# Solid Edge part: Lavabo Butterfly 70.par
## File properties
Title: LAVABO BUTTERFLY 70 APP. O SOSP.
Author: DESYS
Template: Iso Part.par
Last saved by: PIM_1
Revision: 54
Application: Solid Edge
Tipo di contenuto documento: 0
Accuracy: 0,990
Document Number: 4004
Revision: 0
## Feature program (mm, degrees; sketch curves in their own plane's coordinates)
sketch for "unnamed Protrusion 1" plane through (10.8674, 0, 10.8674) normal (0, -1, 0) x-axis (1, 0, 0)
  line (-363.3674, 139.1326) -> (341.6326, 139.1326)
  line (341.6326, 139.1326) -> (341.6326, 99.1326)
  arc centre (366.2448, -119.1314) radius 219.6474 from (341.6326, 99.1326) to (175.1326, -10.8674) ccw
  line (175.1326, -10.8674) -> (-196.8674, -10.8674)
  arc centre (-387.9795, -119.1314) radius 219.6474 from (-196.8674, -10.8674) to (-363.3674, 99.1326) ccw
  line (-363.3674, 99.1326) -> (-363.3674, 139.1326)
  dimension (linear) = 363.3674
  dimension (linear) = 341.6326
  dimension (linear) = 175.1326
extrude "unnamed Protrusion 1" add finite 465 along -normal
sketch for "ScavoEstrusione_1" plane through (-352.5, 230, 130) normal (-1, 0, 0) x-axis (0, 1, 0)
  arc centre (296.5104, 280.8333) radius 267.988 from (235, 20) to (75, 130) cw
extrude "ScavoEstrusione_1" cut finite 1680 symmetric
sketch for "ScavoEstrusione_3" plane through (0, 152.5, 0) normal (0, 0, -1) x-axis (-1, 0, 0)
extrude "ScavoEstrusione_3" cut finite 143 along -normal
sketch for "ScavoEstrusione_4" plane through (0, 152.5, 0) normal (0, 0, -1) x-axis (-1, 0, 0)
  line (-56.3207, 112.5) -> (84.0012, 112.5)
  arc centre (216.8258, 77.748) radius 137.2956 from (135, -32.5) to (84.0012, 112.5) cw
  line (-135, -32.5) -> (135, -32.5)
  arc centre (-192.1289, 92.3454) radius 137.2956 from (-135, -32.5) to (-56.3207, 112.5) ccw
  dimension (linear) = 56.3207
extrude "ScavoEstrusione_4" cut finite 25 along -normal
sketch for "ScavoEstrusione_6" plane through (0, 0, 75) normal (0, -1, 0) x-axis (-1, 0, 0)
extrude "ScavoEstrusione_6" cut finite 35 along -normal
fillet "Rotondo_3" radius 30
sketch for "ScavoEstrusione_8" #1 plane through (0, 152.5, 0) normal (0, 0, -1) x-axis (-1, 0, 0)
  line (-166, 132.5) -> (-104, 132.5)
  line (-104, 132.5) -> (-104, 70.5)
  line (-104, 70.5) -> (-166, 70.5)
  line (-166, 70.5) -> (-166, 132.5)
  dimension (linear) = 166
  dimension (linear) = 166
sketch for "ScavoEstrusione_8" #2 plane through (0, 152.5, 0) normal (0, 0, -1) x-axis (-1, 0, 0)
  line (172.5, 132.5) -> (110.5, 132.5)
  line (110.5, 132.5) -> (110.5, 70.5)
  line (110.5, 70.5) -> (172.5, 70.5)
  line (172.5, 70.5) -> (172.5, 132.5)
extrude "ScavoEstrusione_8" cut finite 30 along -normal
sketch for "ScavoEstrusione_10" #1 plane through (0, 152.5, 0) normal (0, 0, -1) x-axis (-1, 0, 0)
sketch for "ScavoEstrusione_10" #2 plane through (0, 152.5, 0) normal (0, 0, -1) x-axis (-1, 0, 0)
extrude "ScavoEstrusione_10" cut finite 30 along -normal
fillet "Rotondo_4" radius 10
sketch for "ScavoEstrusione_11" #1 plane through (0, 0, 75) normal (0, -1, 0) x-axis (-1, 0, 0)
  circle centre (317.7044, -50) radius 10
sketch for "ScavoEstrusione_11" #2 plane through (0, 0, 75) normal (0, -1, 0) x-axis (-1, 0, 0)
  circle centre (-317.7044, -50) radius 10
extrude "ScavoEstrusione_11" cut finite 385 along -normal
sketch for "ScavoEstrusione_12" #1 plane through (0, 0, 75) normal (0, -1, 0) x-axis (-1, 0, 0)
  line (87.5, 0.6024) -> (97.5, 0.6024)
  arc centre (97.5, -11.8976) radius 12.5 from (97.5, 0.6024) to (97.5, -24.3976) cw
  line (97.5, -24.3976) -> (87.5, -24.3976)
  arc centre (87.5, -11.8976) radius 12.5 from (87.5, -24.3976) to (87.5, 0.6024) cw
sketch for "ScavoEstrusione_12" #2 plane through (0, 0, 75) normal (0, -1, 0) x-axis (-1, 0, 0)
  line (-97.5, -24.3976) -> (-87.5, -24.3976)
  arc centre (-87.5, -11.8976) radius 12.5 from (-87.5, -24.3976) to (-87.5, 0.6024) ccw
  line (-87.5, 0.6024) -> (-97.5, 0.6024)
  arc centre (-97.5, -11.8976) radius 12.5 from (-97.5, 0.6024) to (-97.5, -24.3976) ccw
extrude "ScavoEstrusione_12" cut finite 70 along -normal
sketch for "ScavoEstrusione_13" plane through (-141.5, 223, 15) normal (0, 1, 0) x-axis (1, 0, 0)
  circle centre (-0.8792, 7.7457) radius 2.019
extrude "ScavoEstrusione_13" cut finite 35 along -normal
sketch for "ProtrusioneEstrusa_2" plane through (0, 192.5, 25) normal (0, 0, -1) x-axis (-1, 0, 0)
extrude "ProtrusioneEstrusa_2" add finite 38 along +normal
sketch for "ScavoEstrusione_15" plane through (0, 230, 150) normal (0, 0, 1) x-axis (1, 0, 0)
extrude "ScavoEstrusione_15" cut finite 700 along -normal
lofted cutout "unnamed LoftedCutout 1"
sketch for "ScavoEstrusione_16" plane through (-3.2998, 202.5, -13) normal (0, 0, -1) x-axis (1, 0, 0)
  circle centre (3.2998, 2.5) radius 22.5
extrude "ScavoEstrusione_16" cut finite 525 along -normal
sketch for "ScavoEstrusione_17" plane through (0, 137.5, 95) normal (0, 0.99083, 0.135113) x-axis (-1, 0, 0)
extrude "ScavoEstrusione_17" cut finite 35 along -normal
replace surface "unnamed ReplaceSurface 1"
sketch for "ProtrusioneEstrusa_6" plane through (0, 230, 130) normal (-1, 0, 0) x-axis (0, 1, 0)
  line (-56.6511, 130) -> (-135, 130)
  line (-135, -13) -> (-135, 130)
  line (-135, -13) -> (-110, -13)
  line (-110, -13) -> (-110, 105)
  line (-110, 105) -> (-59.3301, 105)
  dimension (linear) = 135
extrude "ProtrusioneEstrusa_6" add finite 45 symmetric
sketch for "unnamed Protrusion 2" plane through (-3.2998, 95, 74) normal (0, -1, 0) x-axis (-1, 0, 0)
extrude "unnamed Protrusion 2" add through along -normal
fillet "Rotondo_5" radius 85
fillet "Rotondo_7" radius 60
fillet "Rotondo_8" radius 5
fillet "Rotondo_11" radius 5
fillet "Rotondo_12" radius 5
fillet "Rotondo_13" radius 5
fillet "Rotondo_14" radius 5
fillet "Rotondo_15" radius 10
fillet "Rotondo_17" radius 9
fillet "Rotondo_19" radius 5
fillet "Rotondo_20" radius 5
fillet "Rotondo_21" radius 5
fillet "Rotondo_23" radius 5
fillet "Rotondo_24" radius 8
fillet "Rotondo_25" radius 1
fillet "Rotondo_29" radius 5
fillet "Rotondo_28" radius 5
fillet "Rotondo_30" radius 20
fillet "Rotondo_26" radius 5
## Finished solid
Body 1: sheet body, 1 face, 4 edges, 4 vertices.
  Faces by surface: spline 1
  Edges by curve: intersection 2, circle 1, line 1
Body 2: solid body, 264 faces, 550 edges, 288 vertices.
  Faces by surface: cylinder 103, torus 46, plane 43, blend 39, sphere 28, swept 3, spline 2
  Edges by curve: circle 276, line 189, intersection 76, ellipse 9
Bounding box of the edges (mm; curved faces can reach further): 705.000 x 465.000 x 163.000, from (-352.5, 0, -13) to (352.5, 465, 150).
Cylindrical faces by radius (mm): R2.019 x1, R5 x71, R9 x8, R10 x4, R12.5 x5, R20 x1, R22.5 x1, R30 x4, R32.5 x1, R60 x3, R137.2956 x2, R219.6474 x2
Toroidal faces (ring radius, tube radius in mm): R5 r5 x2, R10 r5 x13, R15 r5 x3, R17.5 r5 x4, R22 r5 x1, R23 r5 x1, R25 r5 x7, R30.5 r8 x1, R31.5 r1 x1, R35 r5 x2, R37.5 r5 x1, R55 r5 x1, R65 r5 x3, R132.2956 r5 x2, R224.6474 r5 x2, R229.6474 r10 x2
Spherical faces by radius (mm): R5 x24, R9 x4
Planar faces by outward normal: +x 5, +y 5, +z 4, -x 5, -y 9, -z 10, oblique 5
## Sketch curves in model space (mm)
line (312.5, 130, 150) -> (-312.5, 130, 150)
line (-312.5, 130, 150) -> (-312.5, 434, 150)
arc centre (0, 3915.8021, 150) radius 3495.7978 from (312.5, 434, 150) through (0, 420.0043, 150) to (-312.5, 434, 150)
line (312.5, 434, 150) -> (312.5, 130, 150)
line (112.5, 145, 40) -> (-112.5, 145, 40)
line (-112.5, 145, 40) -> (-112.5, 267.3929, 40)
line (-112.5, 267.3929, 40) -> (112.5, 267.3929, 40)
line (112.5, 267.3929, 40) -> (112.5, 145, 40)
arc centre (0, 465, -12313.125) radius 12428.125 from (352.5, 465, 110) through (0, 465, 115) to (-352.5, 465, 110)
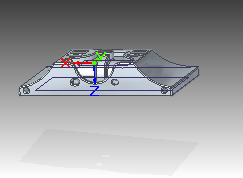
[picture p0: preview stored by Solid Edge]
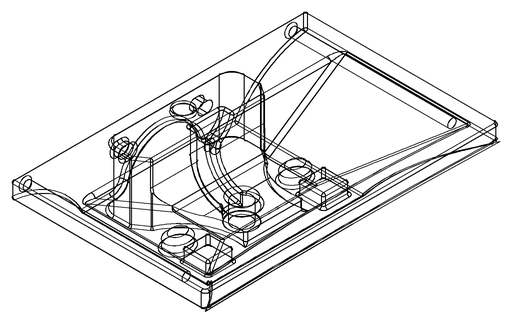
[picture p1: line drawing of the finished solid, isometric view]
